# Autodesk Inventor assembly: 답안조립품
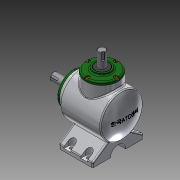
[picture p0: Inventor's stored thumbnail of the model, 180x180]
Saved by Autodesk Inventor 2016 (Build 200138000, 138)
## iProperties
Created: 2017-04
Part Number: 답안조립품
Material: 일반
Document SubType Name: Assembly
Designer: H
Author: H
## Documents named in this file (14)
- C:\Users\CAMTIC\Desktop\470407V1031\답안조립품.iam
- C:\Users\CAMTIC\Desktop\470407V1031\1-본체.ipt
- C:\Users\CAMTIC\Desktop\470407V1031\메인 베벨기어.ipt
- C:\Users\CAMTIC\Desktop\470407V1031\메인 축.ipt
- 메인 축.ipt
- C:\Users\CAMTIC\Desktop\470407V1031\베어링 6203.ipt
- C:\Users\CAMTIC\Desktop\470407V1031\볼트 M4.ipt
- C:\Users\CAMTIC\Desktop\470407V1031\서브 베벨기어.ipt
- C:\Users\CAMTIC\Desktop\470407V1031\서브 축.ipt
- 서브 축.ipt
- C:\Users\CAMTIC\Desktop\470407V1031\오일실 17 32 8.ipt
- C:\Users\CAMTIC\Desktop\470407V1031\커버.ipt
- C:\Users\CAMTIC\Desktop\470407V1031\키 4x4.ipt
- C:\Users\CAMTIC\Desktop\470407V1031\키 5x5.ipt
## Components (1 placed, 1 different names)
1. 1-본체:1
